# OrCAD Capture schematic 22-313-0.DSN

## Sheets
1 BODY_MOTOR_INTERFACE: size A; title: BODY MOTOR INTERFACE; rev: 0; note: PCB/22-313-0
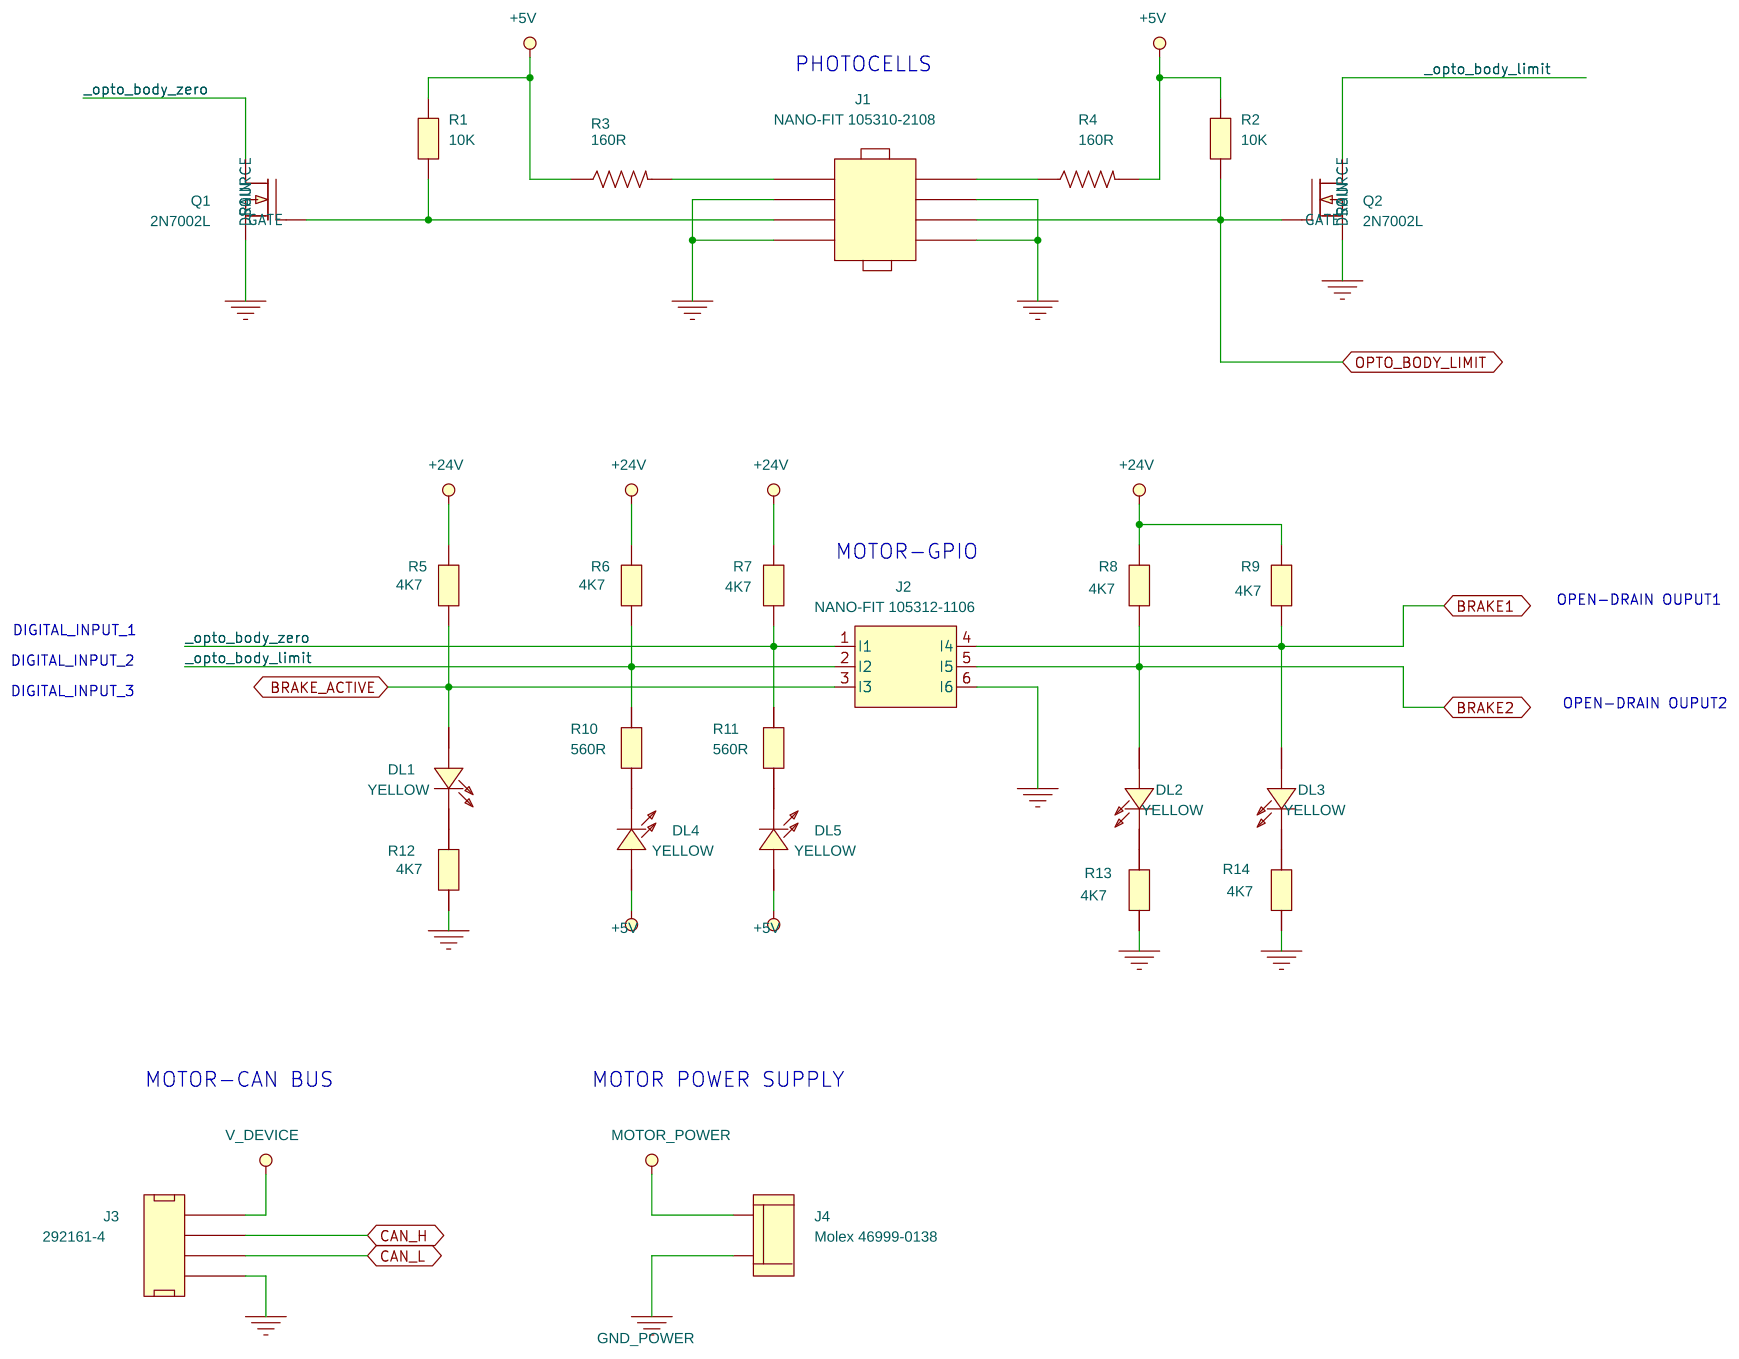
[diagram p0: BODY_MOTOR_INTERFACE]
2 BRAKE: size A; title: BRAKE CONTROL
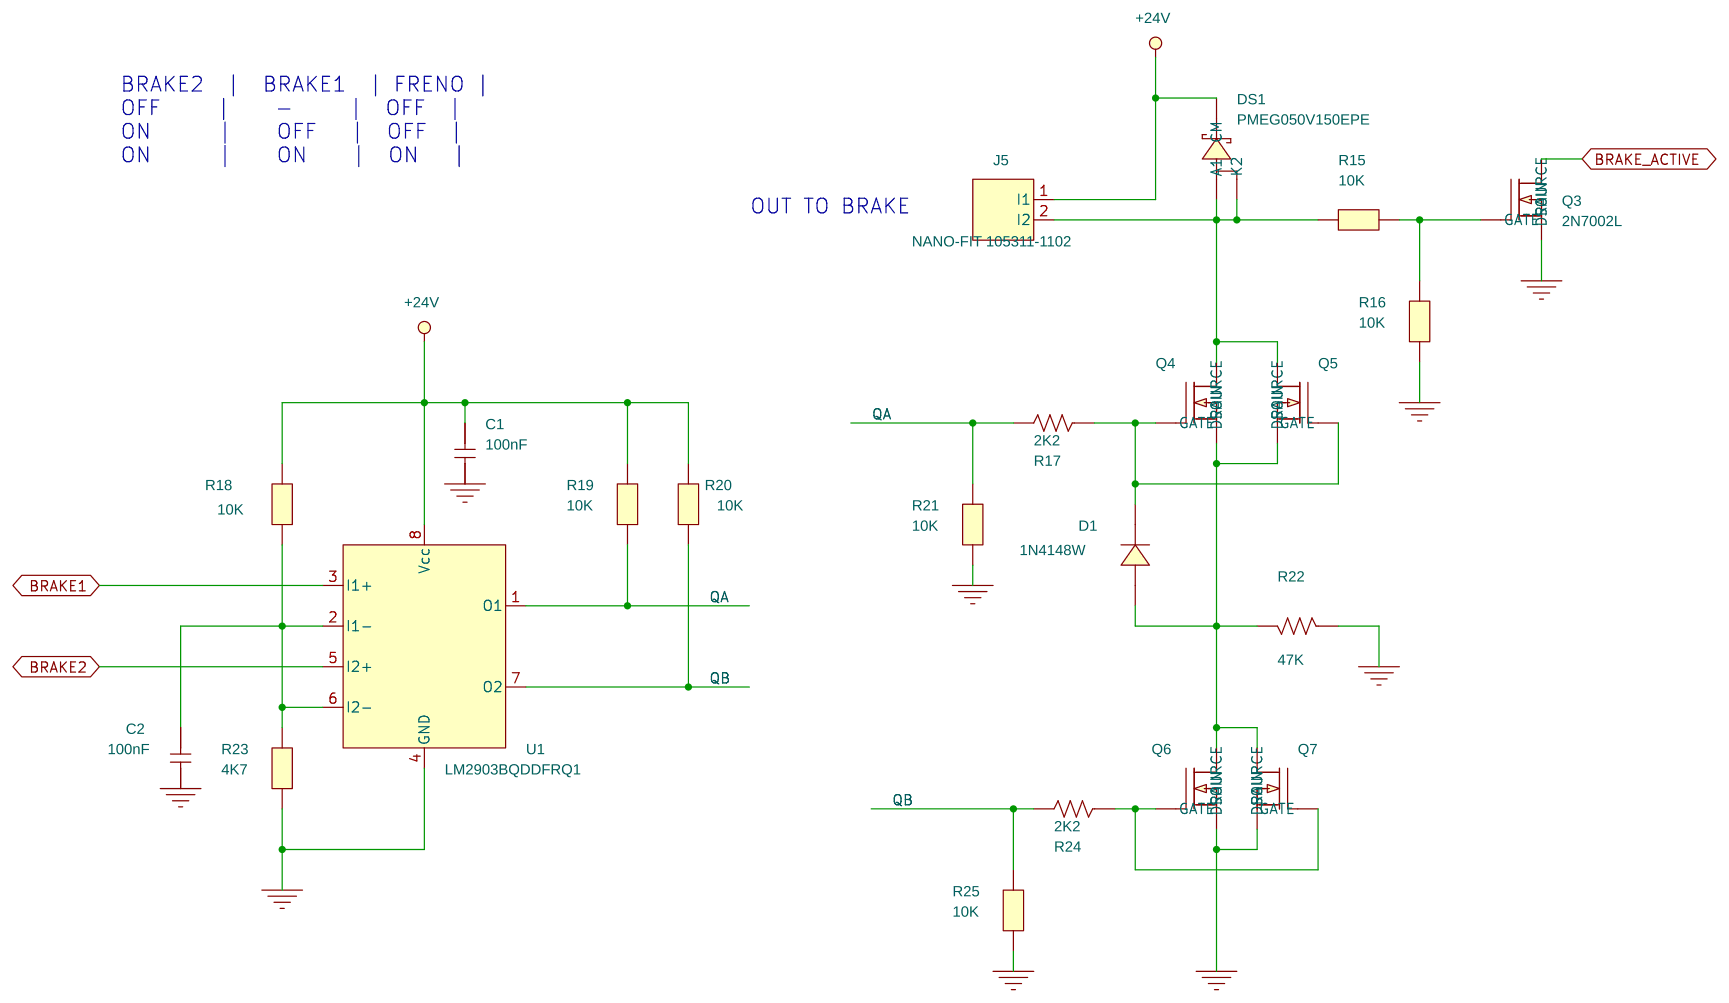
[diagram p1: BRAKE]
3 INPUT: size A; title: INPUT BOARD
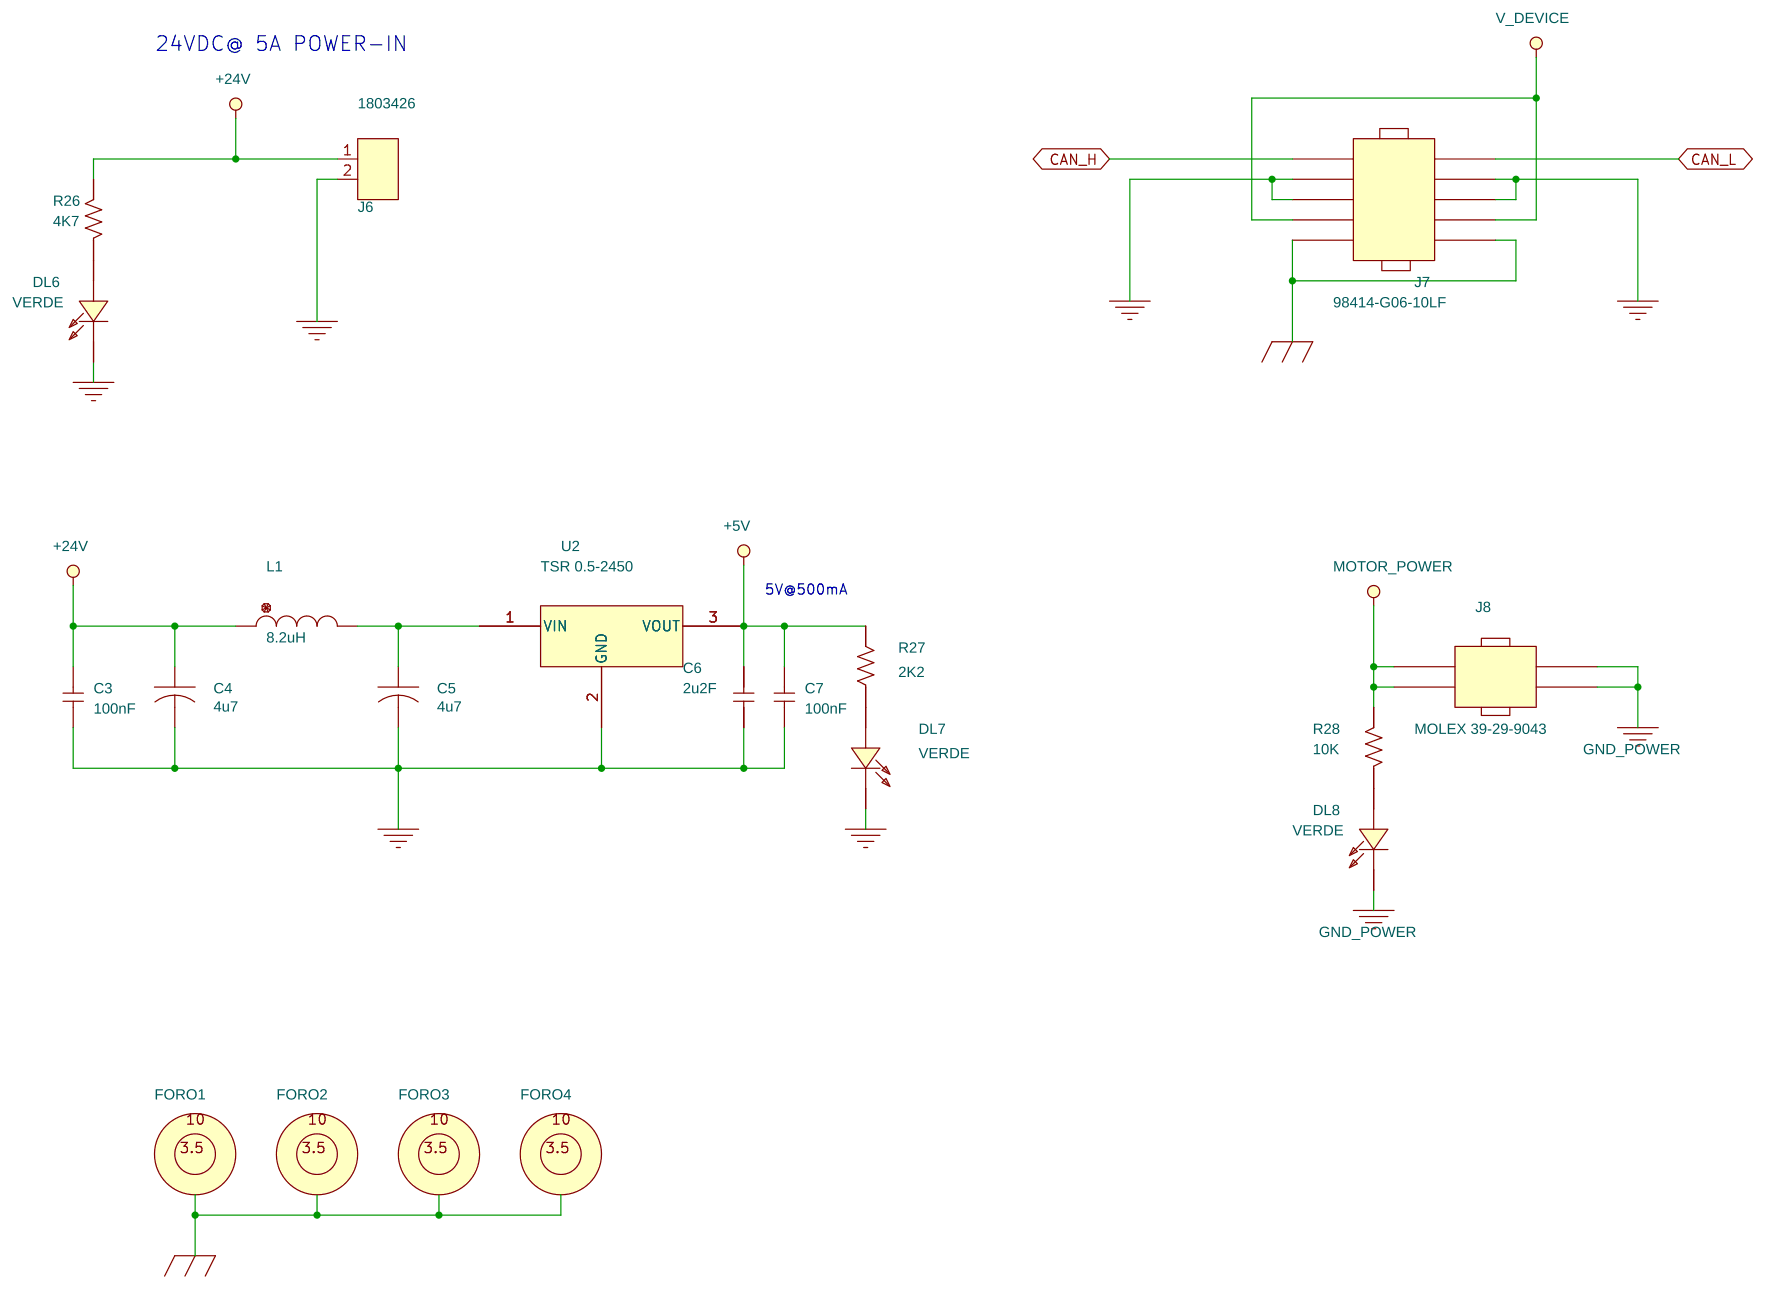
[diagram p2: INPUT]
4 SAFETY: size A; title: MOTOR SAFETY
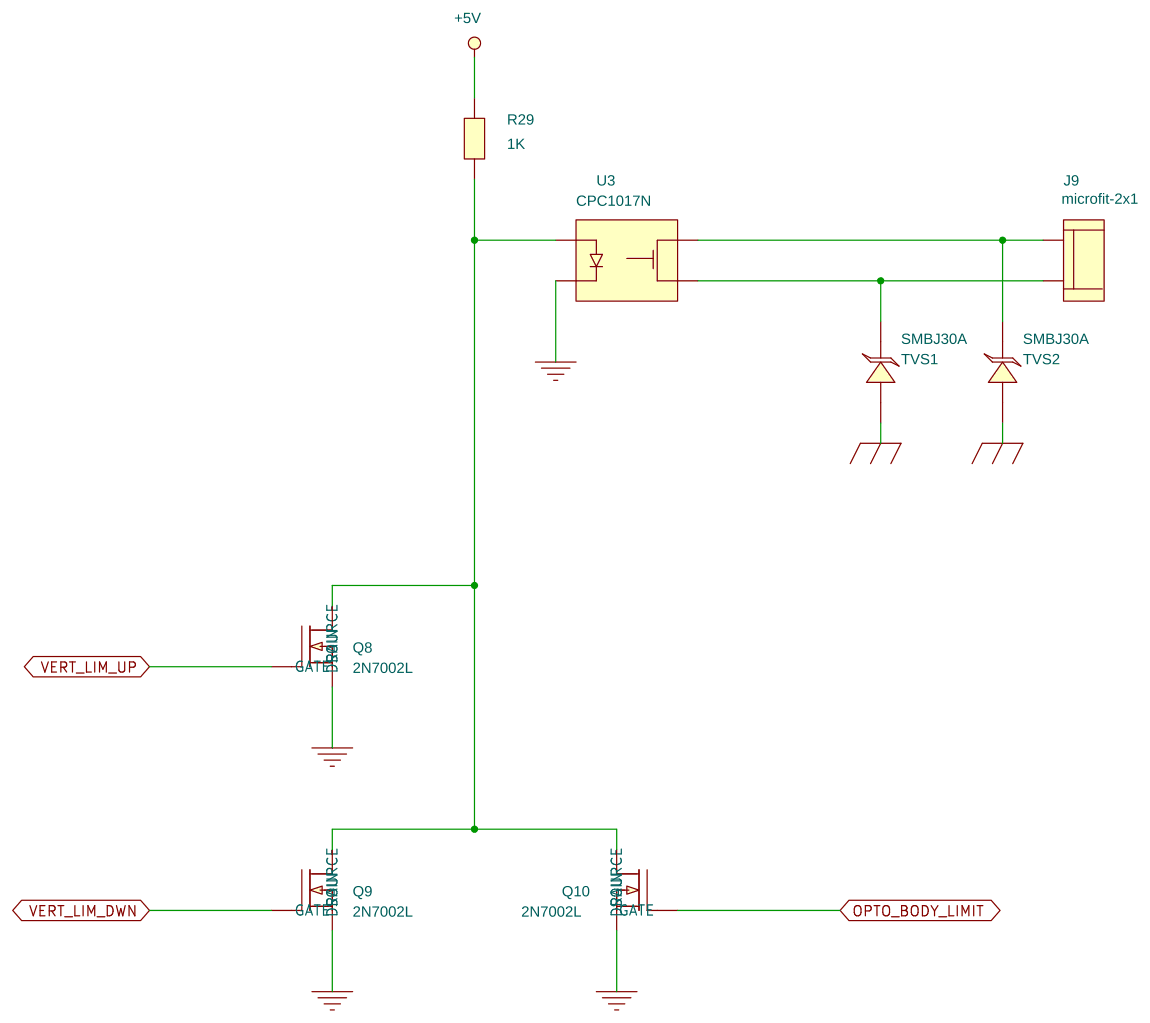
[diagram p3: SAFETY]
5 VERT_MOTOR_INTERFACE: size A; title: VERTICAL MOTOR
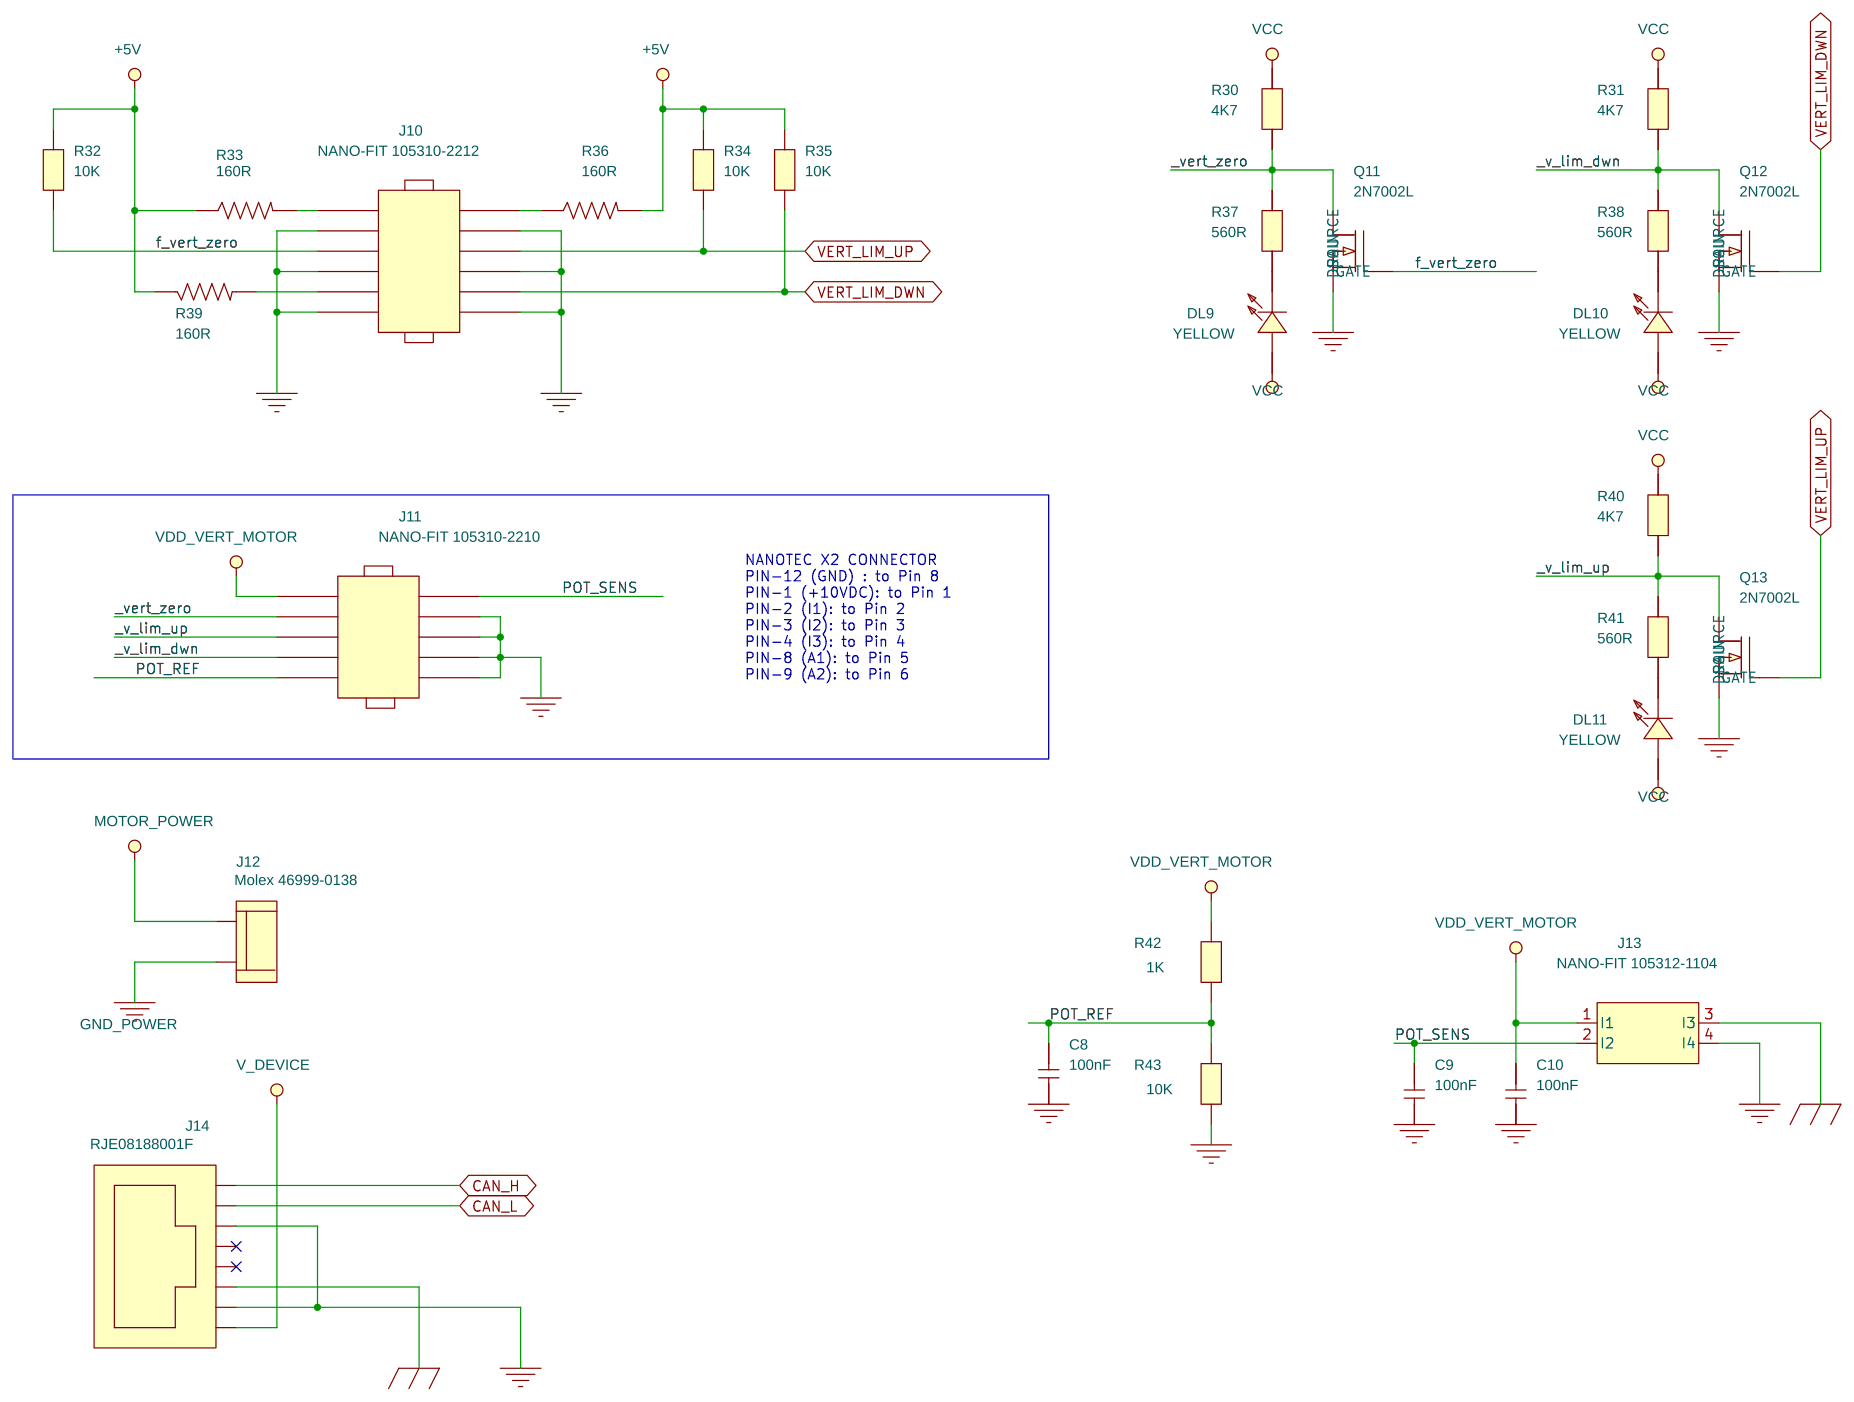
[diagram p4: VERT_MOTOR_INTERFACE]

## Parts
sheet BODY_MOTOR_INTERFACE
DL1  YELLOW  [LED0805-MET-12]
DL2  YELLOW  [LED0805-MET-12]
DL3  YELLOW  [LED0805-MET-12]
DL4  YELLOW  [LED0805-MET-12]
DL5  YELLOW  [LED0805-MET-12]
J1  NANO-FIT 105310-2108
J2  NANO-FIT 105312-1106  [1053121106-MOLEX]
J3  292161-4
J4  Molex 46999-0138  [B2B-PH-K-JST]
Q1  2N7002L
Q2  2N7002L
R1  10K  [SMD0603]
R2  10K  [SMD0603]
R3  160R  [SMD1206]
R4  160R  [SMD1206]
R5  4K7  [SMD0603]
R6  4K7  [SMD0603]
R7  4K7  [SMD0603]
R8  4K7  [SMD0603]
R9  4K7  [SMD0603]
R10  560R  [SMD0603]
R11  560R  [SMD0603]
R12  4K7  [SMD0603]
R13  4K7  [SMD0603]
R14  4K7  [SMD0603]
sheet BRAKE
C1  100nF
C2  100nF
D1  1N4148W  [SOD523F1-2]
DS1  PMEG050V150EPE
J5  NANO-FIT 105311-1102  [1053111102-MOLEX]
Q3  2N7002L
Q4  SSM3K341R,LF
Q5  SSM3K341R,LF
Q6  SSM3K341R,LF
Q7  SSM3K341R,LF
R15  10K  [SMD0603]
R16  10K  [SMD0603]
R17  2K2
R18  10K  [SMD0603]
R19  10K  [SMD0603]
R20  10K  [SMD0603]
R21  10K  [SMD0603]
R22  47K
R23  4K7  [SMD0603]
R24  2K2
R25  10K  [SMD0603]
U1  LM2903BQDDFRQ1
sheet INPUT
C3  100nF
C4  4u7
C5  4u7
C6  2u2F
C7  100nF
DL6  VERDE
DL7  VERDE
DL8  VERDE
FORO1  FORO_HEART_0
FORO2  FORO_HEART_0
FORO3  FORO_HEART_0
FORO4  FORO_HEART_0
J6  1803426
J7  98414-G06-10LF
J8  MOLEX 39-29-9043
L1  8.2uH  [SRR4528A-BOURNS]
R26  4K7
R27  2K2
R28  10K
U2  TSR 0.5-2450  [TSR-0.5-TRACO]
sheet SAFETY
J9  microfit-2x1  [B2B-PH-K-JST]
Q8  2N7002L
Q9  2N7002L
Q10  2N7002L
R29  1K  [SMD0603]
TVS1  SMBJ30A  [SMB-12]
TVS2  SMBJ30A  [SMB-12]
U3  CPC1017N
sheet VERT_MOTOR_INTERFACE
C8  100nF
C9  100nF
C10  100nF
DL9  YELLOW  [LED0805-MET-12]
DL10  YELLOW  [LED0805-MET-12]
DL11  YELLOW  [LED0805-MET-12]
J10  NANO-FIT 105310-2212
J11  NANO-FIT 105310-2210
J12  Molex 46999-0138  [B2B-PH-K-JST]
J13  NANO-FIT 105312-1104  [1053121104-MOLEX]
J14  RJE08188001F
Q11  2N7002L
Q12  2N7002L
Q13  2N7002L
R30  4K7  [SMD0603]
R31  4K7  [SMD0603]
R32  10K  [SMD0603]
R33  160R  [SMD1206]
R34  10K  [SMD0603]
R35  10K  [SMD0603]
R36  160R  [SMD1206]
R37  560R  [SMD0603]
R38  560R  [SMD0603]
R39  160R  [SMD1206]
R40  4K7  [SMD0603]
R41  560R  [SMD0603]
R42  1K  [SMD0603]
R43  10K  [SMD0603]

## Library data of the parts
DL1-DL5 DL9-DL11 = APT2012YC: COMMENT: [PAD_DWN]
J1 = HEADER_5X2_6: Codice Acquisto Fornitore: M: 538-105310-2108; Costruttore: MOLEX; Descrizione: CONN.HEADER 2X5 DRITTO P2; Note: SERIE NANO-FIT; PN: 105310-2108; PN Costruttore: 105310-2108; PN FORNITORE: M: 538-105310-2108; Package: THT; Part Number: 105310-2108
J2 = HEADER-8x2_12: Codice Acquisto Fornitore: M: 538-105312-1106; Costruttore: MOLEX; Descrizione: CONN.HEADER 2X3 DRITTO P2; Note: SERIE NANO-FIT; PN: 105312-1106; PN Costruttore: 105312-1106; PN FORNITORE: M: 538-105312-1106; Part Number: 105312-1106; Rating: NANO-FIT
J3 = 2-292173-4: COMMENT: [INTERFACE]
J4 J12 = B2B-PH-2x1-VERTICALE: Costruttore: Molex; Descrizione: Molex Minifit 2x1; PN: 46999-0138; PN FORNITORE: 538-46999-0138; Package: Minifit46999-0138
Q1-Q3 Q8-Q13 = MOSFET_N_8: Codice Acquisto Fornitore: M: 512-2N7002L; Costruttore: ON; Descrizione: MOSFET CANALE N; Note: 60V VDS, 115mA, Vth=1.8; Package: SOT23
R1 R2 R5-R16 R18-R21 R23 R25 R29-R32 R34 R35 R37 R38 R40-R43 = R0603
R3 R4 R33 R36 R39 = R1206
C1-C3 C7-C10 = C_v2: Codice Acquisto Fornitore: M:80-C0603C104K5R; Costruttore: KEMET; Descrizione: MLCC - SMD/SMT 50V 0.1uF X7R 0603 10%; Note: 50V, X7R; PN Costruttore: C0603C104K5RACTU; Package: SMD0603
D1 = D_1N4148WT
DS1 = PMEG050V150EPEZ
J5 = HEADER-8x2_8: Codice Acquisto Fornitore: M: 538-105311-1102; Costruttore: MOLEX; Descrizione: CONN.HEADER 2X1 DRITTO P2; Note: SERIE NANO-FIT; PN: 105311-1102; PN Costruttore: 105311-1102; PN FORNITORE: M: 538-105311-1102; Part Number: 105311-1102; Rating: NANO-FIT
Q4-Q7 = NMOS_DPAK: CURRENT: 6A; Costruttore: Toshiba; Descrizione: MOSFET  CANALE N 6A, 60V; PN FORNITORE: M: 757-SSM3K341RLF; Package: SOT-23F
R17 R24 R26 R28 = R: Codice Acquisto Fornitore: MULTICOMP; Costruttore: VARI; DESCRIZIONE: Resistore thick film 1/8W 1% 0603; PN Costruttore: VARI; Package: SMD0603; Rating: 1%, 150V, 100ppm/C
R22 = R: Codice Acquisto Fornitore: MULTICOMP; Costruttore: VARI; DESCRIZIONE: Resistore thick film 1/4W 1% 1206; PN Costruttore: VARI; Package: SMD1206; Rating: 1%, 150V, 100ppm/C
U1 = LM2903BQDDFRQ1
C4 C5 = C: Codice Acquisto Fornitore: R- 538-2537; Costruttore: KEMET; Descrizione: Cond.Elt.Tantalio 35V SIZE C; Note: 35V; PN Costruttore: T491C475K035AT; Package: TNT SIZE C
C6 = C_v2: Codice Acquisto Fornitore: R-691-1246; Costruttore: KEMET; Descrizione: MLCC - SMD/SMT 50V 2u2F X7R1 21010%; Note: 50V, X7R; PN Costruttore: C1210C225K5RACTU; Package: SMD1210
DL6 DL8 = LED_1: Codice Acquisto Fornitore: F-2449804; Costruttore: KINGBRIGHT; DESCRIZIONE: Diodo led smd 0805; PN Costruttore: KP-2012SGD; Package: SMD0805
DL7 = LED_1: Codice Acquisto Fornitore: F-2449804; Costruttore: KINGBRIGHT; DESCRIZIONE: Diodo led smd 0805 VERDE; PN Costruttore: KP-2012SGD; Package: SMD0805
FORO1-FORO4 = FORO_HEART_0
J6 = CON2: Costruttore: Phoenix Contact; Descrizione: Connettore 90° 2 pin; PN FORNITORE: M: 651-1803426; Package: THT
J7 = HEADER_5X2: Codice Acquisto Fornitore: D-609-2580-ND; Costruttore: FCI; Descrizione: CONN.HEADER 2X5 DRITTO P2; Note: PASSO 2MM; Package: THT
J8 = HEADER_10X2_6: Codice Acquisto Fornitore: R-6705578; Costruttore: MOLEX; Descrizione: Connettore  MINIFIT 2 x 2 P.4.2; PN Costruttore: 39-29-9043; Package: THT
L1 = L: Codice Acquisto Fornitore: R-1765964; Costruttore: BOURNS; Descrizione: Induttore 8.2uH; Note: 2A, 70moHm, ferrite; PN Costruttore: SRR4528A-8R2Y; Package: 5X5MM SMD
R27 = R: Codice Acquisto Fornitore: MULTICOMP; Costruttore: VARI; DESCRIZIONE: Resistore thick film 1/10W 1% 0603; PN Costruttore: VARI; Package: SMD0603; Rating: 1%, 150V, 100ppm/C; Valore: 33K
U2 = 78XX_SIP_3: Codice Acquisto Fornitore: R-817-9400; Costruttore: TRACO POWER; Descrizione: DC/DC 5V 500mA; Note: MAX 36V INPUT; Package: THT
J9 = B2B-PH-2x1-VERTICALE: Costruttore: Molex; Descrizione: Molex Microfit 2x1; PN: 43650-0215; PN FORNITORE: M: 538-43650-0215; Package: Microfit-43650-0215
TVS1 TVS2 = SMBJ_2: Codice Acquisto Fornitore: F-9551042; Costruttore: VISHAY; Descrizione: Esd monodirezionale; Note: 30V Nominal; PN Costruttore: SMBJ30A-E3/52; Package: SMB
U3 = CPC1017: Codice Acquisto Fornitore: M-849-CPC1017N; Costruttore: CLARE; Descrizione: Rele' stato solido 60Vdc 0.1A; Package: 4-PIN SOP
J10 = HEADER_5X2_9: Codice Acquisto Fornitore: M: 538-105310-2212; Costruttore: MOLEX; Descrizione: CONN.HEADER 2X6 DRITTO P2; Note: SERIE NANO-FIT; PN: 105310-2212; PN Costruttore: 105310-2212; PN FORNITORE: M: 538-105310-2212; Package: THT; Part Number: 105310-2212
J11 = HEADER_5X2_5: Codice Acquisto Fornitore: M: 538-105310-2210; Costruttore: MOLEX; Descrizione: CONN.HEADER 2X5 DRITTO P2; Note: SERIE NANO-FIT; PN: 105310-2210; PN Costruttore: 105310-2210; PN FORNITORE: M: 538-105310-2210; Package: THT; Part Number: 105310-2210
J13 = HEADER-8x2_10: Codice Acquisto Fornitore: M: 538-105312-1104; Costruttore: MOLEX; Descrizione: CONN.HEADER 2X2 DRITTO P2; Note: SERIE NANO-FIT; PN: 105312-1104; PN Costruttore: 105312-1104; PN FORNITORE: M: 538-105312-1104; Part Number: 105312-1104; Rating: NANO-FIT
J14 = RJ45_90: Descrizione: RJ45 8 Posizioni Verticale; PN FORNITORE: M: 523-RJE08188001F

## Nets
+5V: C6.1 C7.2 DL4.2(ANODE) DL5.2(ANODE) DL9.2(ANODE) DL10.2(ANODE) DL11.2(ANODE) R1.2 R2.2 R3.1 R4.2 R27.2 R29.1 R32.2 R33.1 R34.2 R35.2 R36.2 R39.1 U2.3(VOUT)
+24V: C1.2 C3.2 C4.1 DS1.3(CM) J5.1(I1) J6.1 L1.1 R5.2 R6.2 R7.2 R8.2 R9.2 R18.2 R19.2 R20.2 R26.2 R30.2 R31.2 R40.2 U1.8(Vcc)
GND_EARTH: FORO1.1(g1) FORO2.1(g1) FORO3.1(g1) FORO4.1(g1) J7.9 J7.10 J13.3(I3) J14.6 TVS1.2(A) TVS2.2(A)
GND_POWER: DL8.1(CATHODE) J4.2 J8.3 J8.4 J12.2
VDD_VERT_MOTOR: C10.2 J11.1 J13.1(I1) R42.2
0: C1.1 C2.1 C3.1 C4.2 C5.2 C6.2 C7.1 C8.1 C9.1 C10.1 DL6.1(CATHODE) DL7.1(CATHODE) J1.2 J1.4 J1.6 J1.8 J2.6(I6) J3.4 J6.2 J7.3 J7.4 J7.5 J7.6 J10.2 J10.4 J10.7 J10.9 J10.11 J10.12 J11.7 J11.8 J11.9 J11.10 J13.4(I4) J14.3 J14.7 Q1.2(SOURCE) Q2.2(SOURCE) Q3.2(SOURCE) Q6.2(SOURCE) Q7.2(SOURCE) Q8.2(SOURCE) Q9.2(SOURCE) Q10.2(SOURCE) Q11.2(SOURCE) Q12.2(SOURCE) Q13.2(SOURCE) R12.1 R13.1 R14.1 R16.1 R21.1 R22.1 R23.1 R25.1 R43.1 U1.4(GND) U2.2(GND) U3.2(K)
_opto_body_limit: J2.2(I2) Q2.3(DRAIN) R6.1 R10.2
_opto_body_zero: J2.1(I1) Q1.3(DRAIN) R7.1 R11.2
_v_lim_dwn: J11.4 Q12.3(DRAIN) R31.1 R38.2
_v_lim_up: J11.3 Q13.3(DRAIN) R40.1 R41.2
_vert_zero: J11.2 Q11.3(DRAIN) R30.1 R37.2
BRAKE1: DL3.2(ANODE) J2.4(I4) R9.1 U1.3(I1+)
BRAKE2: DL2.2(ANODE) J2.5(I5) R8.1 U1.5(I2+)
BRAKE_ACTIVE: DL1.2(ANODE) J2.3(I3) Q3.3(DRAIN) R5.1
CAN_H: J3.2 J7.2 J14.1
CAN_L: J3.3 J7.1 J14.2
f_vert_zero: J10.3 Q11.1(GATE) R32.1
MOTOR_POWER: J4.1 J8.1 J8.2 J12.1 R28.2
OPTO_BODY_LIMIT: J1.7 Q2.1(GATE) Q10.1(GATE) R2.1
POT_REF: C8.2 J11.5 R42.1 R43.2
POT_SENS: C9.2 J11.6 J13.2(I2)
QA: R17.2 R19.1 R21.2 U1.1(O1)
QB: R20.1 R24.2 R25.2 U1.7(O2)
V_DEVICE: J3.1 J7.7 J7.8 J14.8
VERT_LIM_DWN: J10.10 Q9.1(GATE) Q12.1(GATE) R35.1
VERT_LIM_UP: J10.8 Q8.1(GATE) Q13.1(GATE) R34.1
N6017318: DS1.1(A1) DS1.2(K2) J5.2(I2) Q4.3(DRAIN) Q5.3(DRAIN) R15.2
N6017334: C2.2 R18.1 R23.2 U1.2(I1-) U1.6(I2-)
N6017532: D1.2(A) Q4.2(SOURCE) Q5.2(SOURCE) Q6.3(DRAIN) Q7.3(DRAIN) R22.2
N6020237: D1.1(K) Q4.1(GATE) Q5.1(GATE) R17.1
N6020610: Q6.1(GATE) Q7.1(GATE) R24.1
N6021595: Q3.1(GATE) R15.1 R16.2
N6026897: J9.1 TVS2.1(K) U3.4(O1)
N6026901: J9.2 TVS1.1(K) U3.3(O2)
N6032761: C5.1 L1.2 U2.1(VIN)
N6033222: J1.1 R3.2
N6033390: J1.3 Q1.1(GATE) R1.1
N6035876: Q8.3(DRAIN) Q9.3(DRAIN) Q10.3(DRAIN) R29.2 U3.1(A)
N6036663: J10.6 R36.1
N6048945: DL6.2(ANODE) R26.1
N6049779: DL7.2(ANODE) R27.1
N6050779: DL8.2(ANODE) R28.1
N6058983: J1.5 R4.1
N6061786: J10.1 R33.2
N6061923: J10.5 R39.2
N6078977: DL11.1(CATHODE) R41.1
N6079335: DL10.1(CATHODE) R38.1
N6079430: DL9.1(CATHODE) R37.1
N6081297: DL4.1(CATHODE) R10.1
N6081298: DL1.1(CATHODE) R12.2
N6081299: DL2.1(CATHODE) R13.2
N6081300: DL5.1(CATHODE) R11.1
N6081301: DL3.1(CATHODE) R14.2

Not connected (* = marked no-connect by the designer): J14 4* 5*

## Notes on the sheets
sheet 1
- PHOTOCELLS
- MOTOR-GPIO
- OPEN-DRAIN OUPUT1
- DIGITAL_INPUT_1
- DIGITAL_INPUT_2
- DIGITAL_INPUT_3
- OPEN-DRAIN OUPUT2
- MOTOR-CAN BUS
- MOTOR POWER SUPPLY
sheet 2
- BRAKE2  |  BRAKE1  | FRENO |
  OFF     |    -     |  OFF  |
  ON      |    OFF   |  OFF  |
  ON      |    ON    |  ON   |
- OUT TO BRAKE
sheet 3
- 24VDC@ 5A POWER-IN
- 5V@500mA
sheet 5
- NANOTEC X2 CONNECTOR
  PIN-12 (GND) : to Pin 8
  PIN-1 (+10VDC): to Pin 1
  PIN-2 (I1): to Pin 2
  PIN-3 (I2): to Pin 3
  PIN-4 (I3): to Pin 4
  PIN-8 (A1): to Pin 5
  PIN-9 (A2): to Pin 6
